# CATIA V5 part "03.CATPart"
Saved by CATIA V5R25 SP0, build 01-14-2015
Part number: 03
Bounding box of the stored display mesh (mm): x -50 to 50, y -15 to 15, z 0 to 20
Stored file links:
  D:\feridun18052022montaj\03.CATPart
  D:\feridun18052022montaj\cektirme.CATProduct
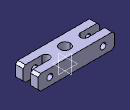
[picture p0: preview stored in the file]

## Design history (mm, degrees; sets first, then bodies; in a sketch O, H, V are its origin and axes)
Body1 (main body)
  Sketch1 on xy-plane, origin (0, 0, 0), H (1, 0, 0), V (0, 1, 0)
    line L1 (50, 15) -> (50, 5)
    line L2 (50, -15) -> (-50, -15)
    line L3 (-50, -15) -> (-50, -5)
    line L4 (-50, 15) -> (50, 15)
    point P5 (-50, 5)
    line L5 (-50, 5) -> (-25, 5)
    point P6 (-25, 5)
    arc A1 centre (-25, 0) radius 5 from (-25, 5) to (-25, -5) cw
    point P7 (-25, 0)
    point P8 (-25, -5)
    line L6 (-25, -5) -> (-50, -5)
    point P9 (-50, -5)
    line L7 (-50, 5) -> (-50, 15)
    point P10 (50, 5)
    point P11 (25, 5)
    point P13 (25, -5)
    point P14 (50, -5)
    line L8 (50, 5) -> (25, 5)
    arc A2 centre (25, 0) radius 5 from (25, 5) to (25, -5) ccw
    line L9 (25, -5) -> (50, -5)
    line L10 (50, -5) -> (50, -15)
    circle A3 centre (0, 0) radius 6.9175
    distance L1 L3 = 100
    distance L2 L4 = 30
    radius A1 = 5
    distance P7 L3 = 25
    radius A3 = 6.9175
    vertical: L1 V, L3 V, L7 V, L10 V
    horizontal: L2 H, L4 H, L5 H
    equidistance: L1 L3 O, L2 L4 O
    coincidence: P5 L3, L3 L7, L1 L10
    tangency: A1 L5, L6 A1
    symmetry: L5 L6 H, P5 P10 V, P6 P11 V, P8 P13 V, P9 P14 V, L5 L8 V, A1 A2 V, L6 L9 V
  Pad1: profile Sketch1, direction (0, 0, 1), length 20
  Chamfer1: length 3, angle 45, on edge [face of Pad1 from Sketch1.L1 | end face of Pad1]; edge [face of Pad1 from Sketch1.L10 | end face of Pad1]; edge [face of Pad1 from Sketch1.L7 | end face of Pad1]; edge [face of Pad1 from Sketch1.L3 | end face of Pad1]; edge [start face of Pad1 | face of Pad1 from Sketch1.L10]; edge [start face of Pad1 | face of Pad1 from Sketch1.L1]; edge [start face of Pad1 | face of Pad1 from Sketch1.L3]; edge [start face of Pad1 | face of Pad1 from Sketch1.L7]
  Thread1: "M16x1.5", diameter 16, depth 20, pitch 1.5, on face of Pad1 from Sketch1.A3, from end face of Pad1
  Sketch2 on face of Pad1 from Sketch1.L4, origin (0, 15, 0), H (-1, 0, 0), V (0, 0, 1)
    circle A1 centre (-35, 10) radius 4
    point P1 (-35, 10)
    circle A2 centre (35, 10) radius 4
    point P2 (35, 10)
    reference projected line E1 (-50, 0) -> (50, 0) from edge [start face of Pad1 | face of Pad1 from Sketch1.L4]
    reference projected line E2 (-50, 0) -> (50, 0) from edge [start face of Pad1 | face of Pad1 from Sketch1.L4]
    radius A1 = 4
    radius A2 = 4
    distance P1 V = 35
    distance P1 E1 = 10
    distance P2 E2 = 10
    distance P2 V = 35
  Pocket1: profile Sketch2, direction (0, -1, 0), through (limit type 3)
